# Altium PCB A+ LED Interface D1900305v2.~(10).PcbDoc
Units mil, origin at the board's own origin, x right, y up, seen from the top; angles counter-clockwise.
Board outline 2700 x 2000 mil, 4 copper layers (Top Layer, GND, GND (Plane2), Bottom Layer), stack 61.2 mil thick; 19 components, 34 nets, 90 pads, 1 vias.
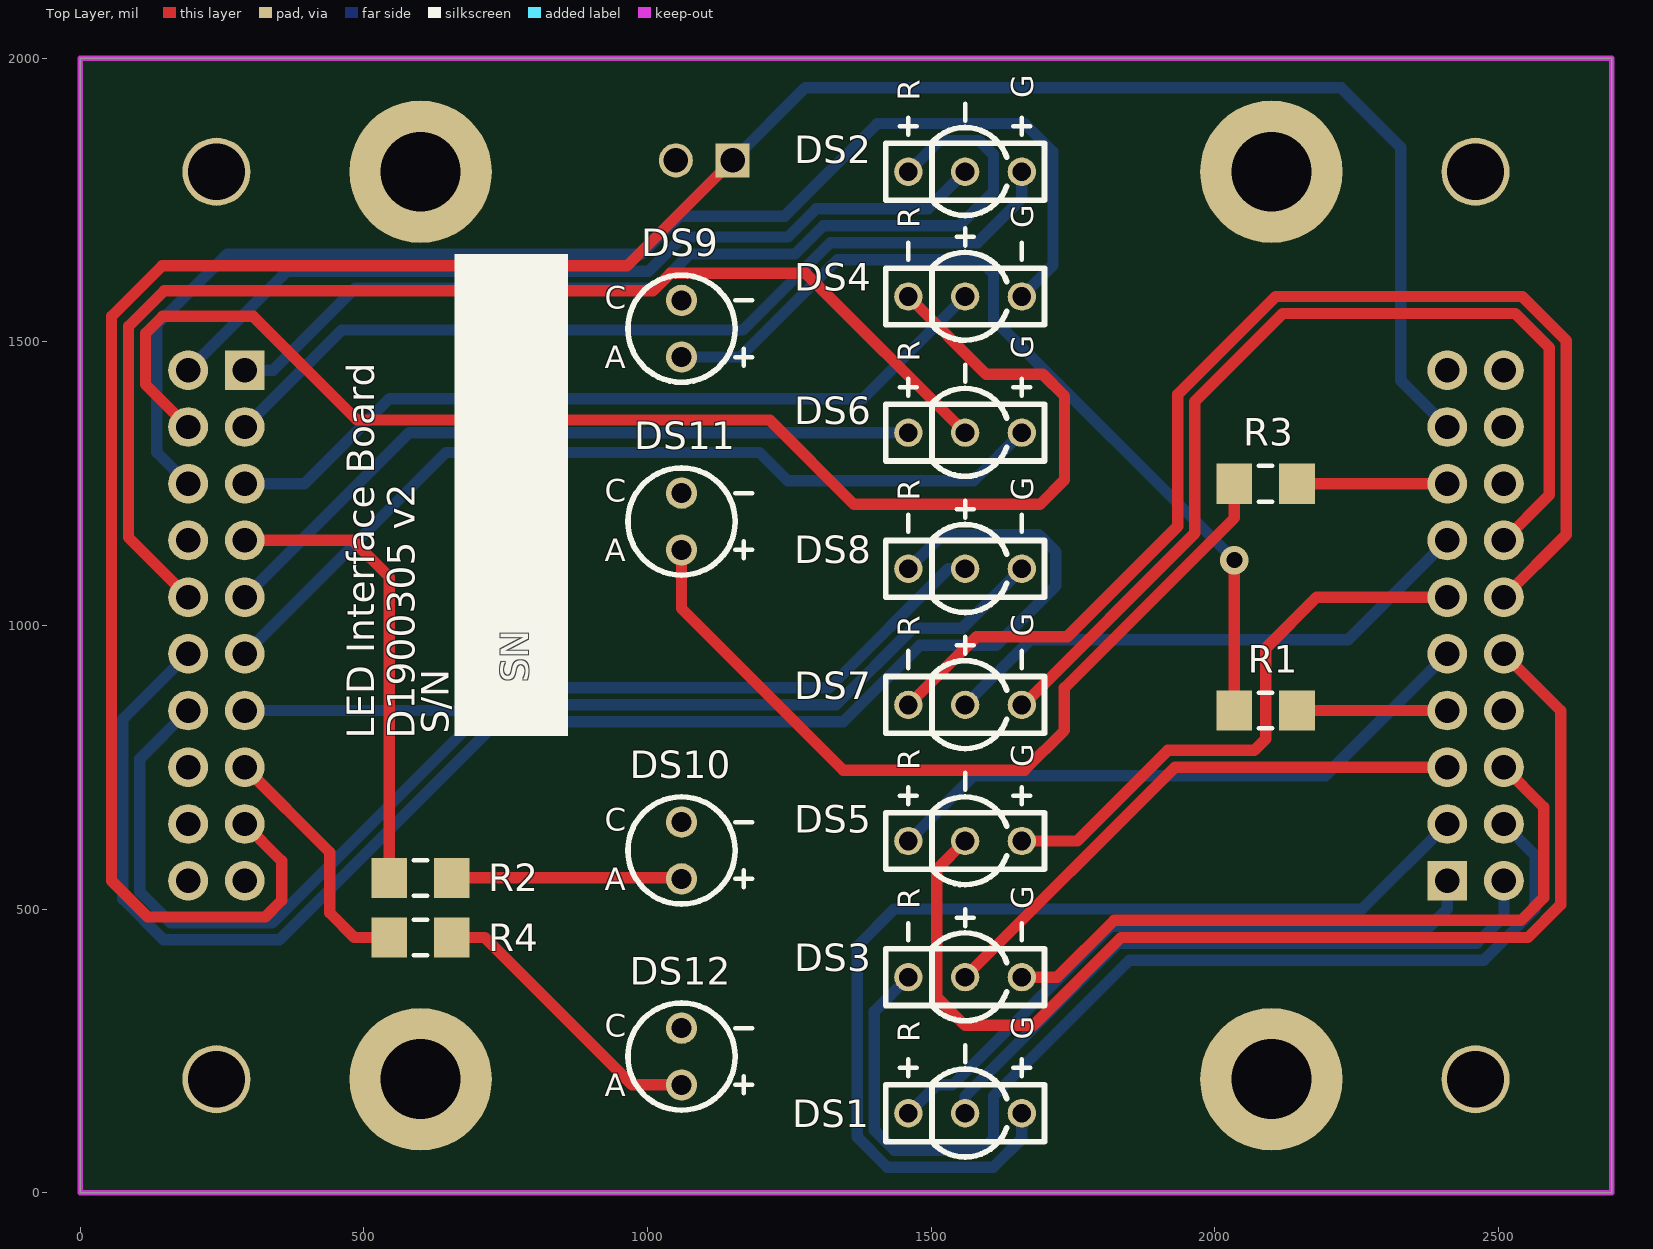
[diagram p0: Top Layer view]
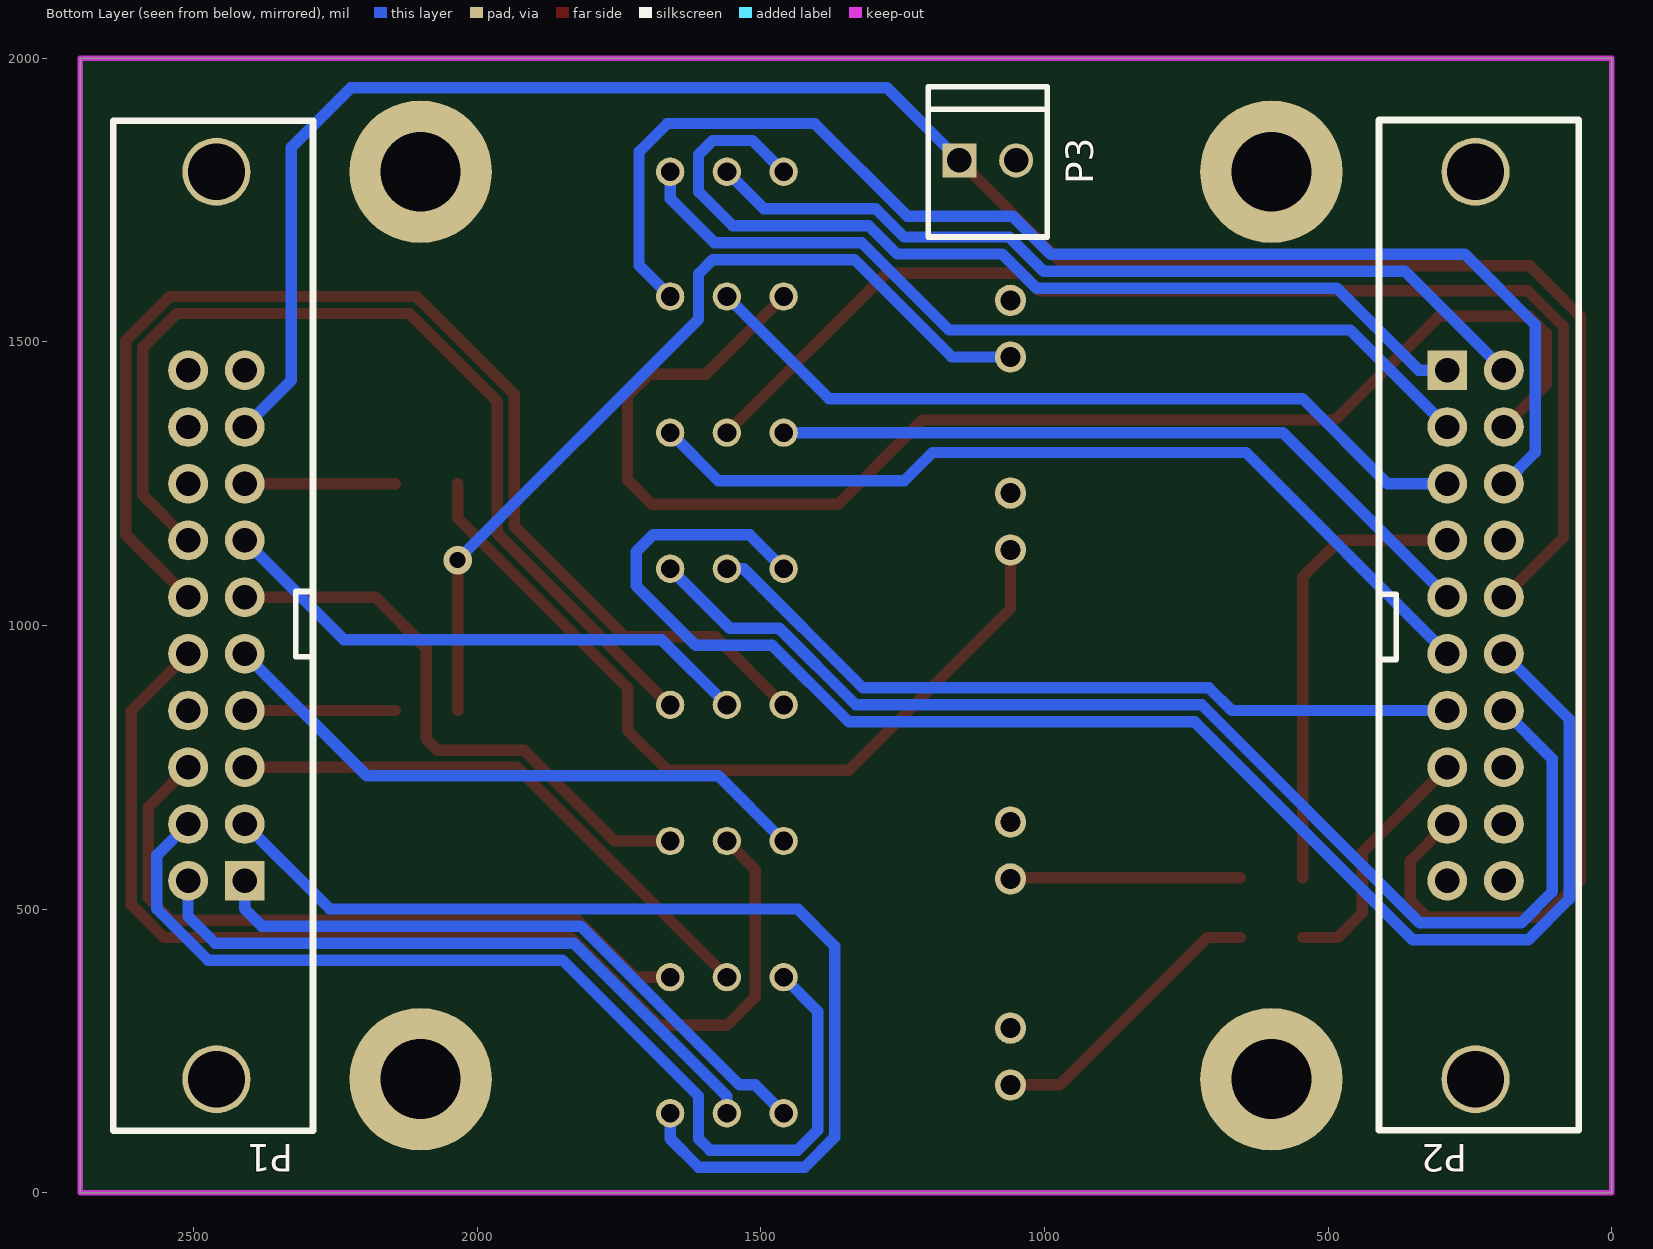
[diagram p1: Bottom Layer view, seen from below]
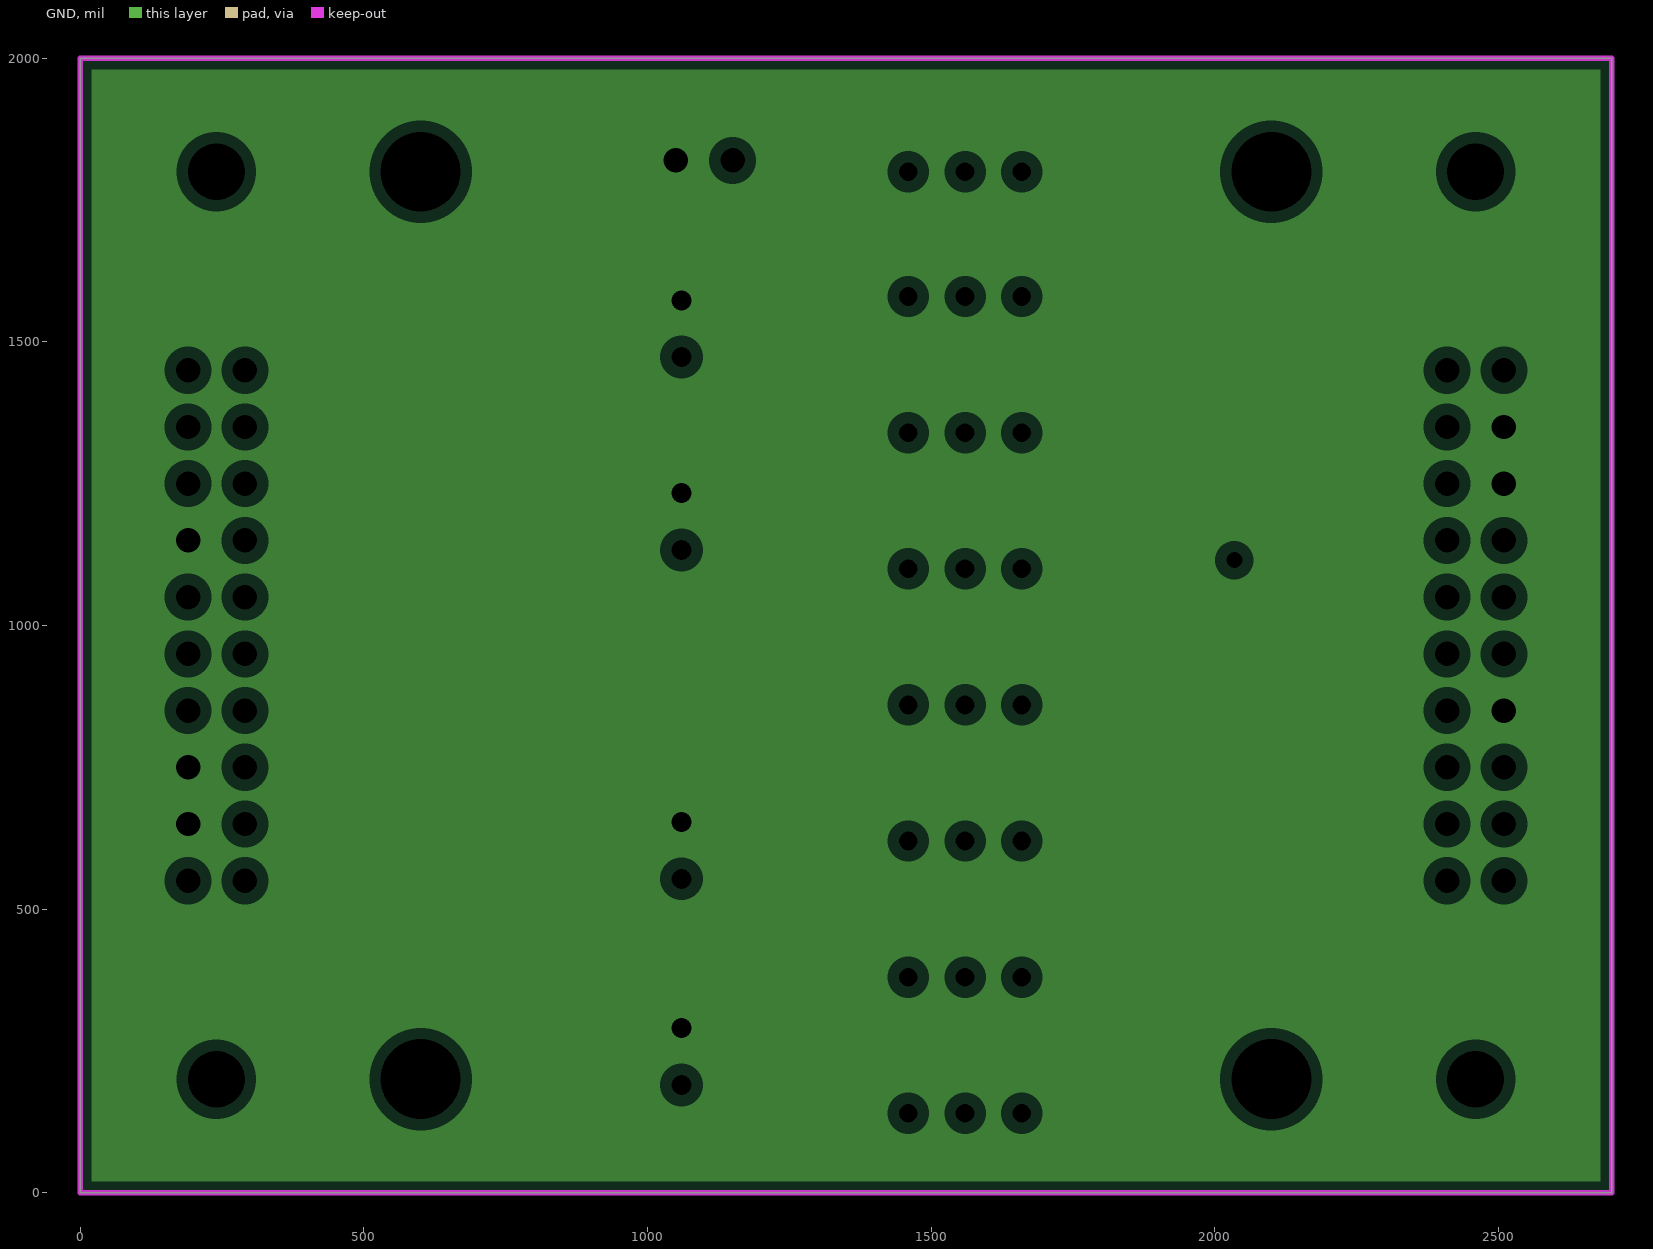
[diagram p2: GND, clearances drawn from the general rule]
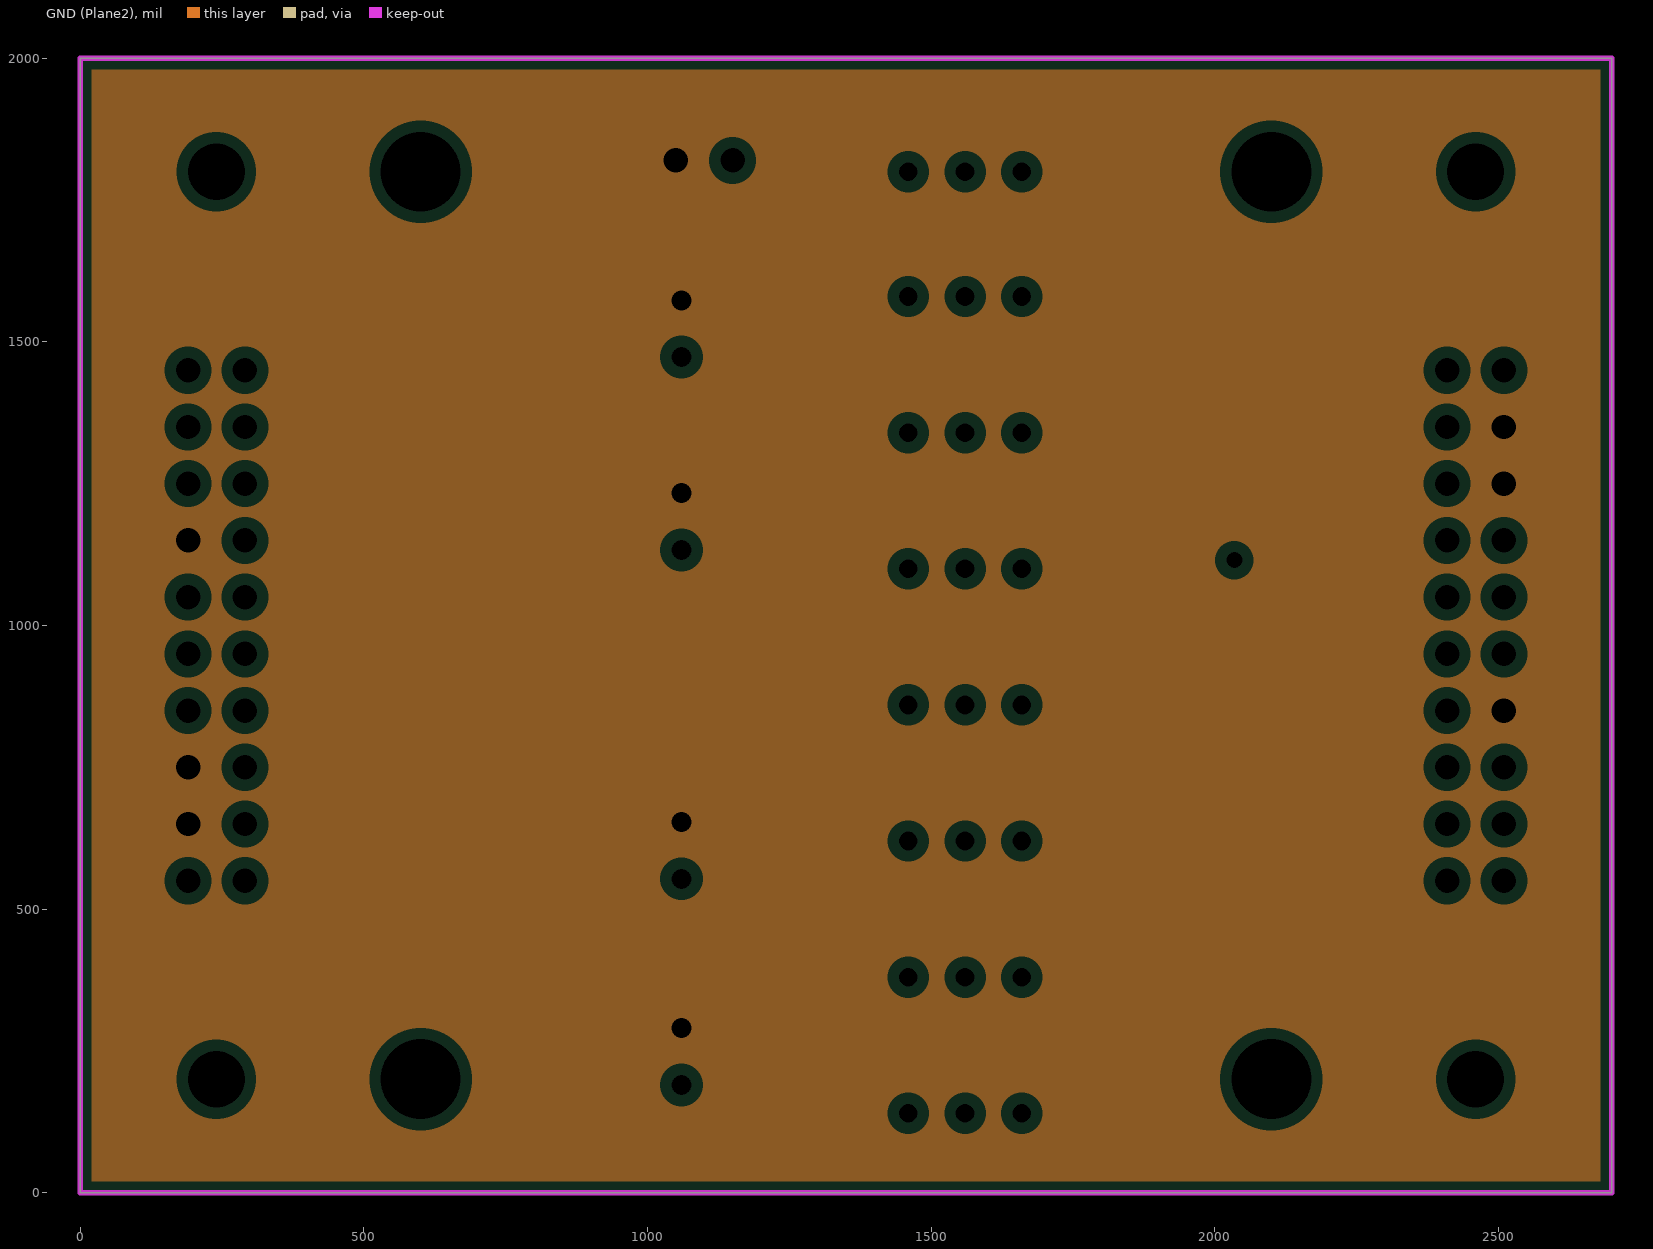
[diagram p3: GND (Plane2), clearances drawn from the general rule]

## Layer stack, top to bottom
Top Solder: solder mask 0.4, Solder Resist, Dk 3.5
Top Layer: signal copper 1.4
Dielectric 1: prepreg 7.5, FR-4, Dk 4.2
GND: plane copper 1.4, net GND
Dielectric 3: prepreg 40.6, Dk 4.2
GND (Plane2): plane copper 1.4, net GND
Dielectric 2: prepreg 7.5, FR-4, Dk 4.2
Bottom Layer: signal copper 1.4
Bottom Solder: solder mask 0.4, Solder Resist, Dk 3.5

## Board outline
0,0 2700,0 2700,2000 0,2000 0,0

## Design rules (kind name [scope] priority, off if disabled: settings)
Clearance [All] p1: gap=10 ignorepadtopadclearanceinfootprint=FALSE except(0: Arc-Hole Track-Hole SMDPad-Hole THPad-Hole Via-Hole Fill-Hole Poly-Hole Region-Hole Text-Hole)
FabricationTestPointUsage TestPointUsage [All] p1: valid=0 allowmultiple=FALSE
FabricationTestpoint Testpoint [All] p1: side=3 testpointundercomponent=TRUE minsize=40 maxsize=100 preferedsize=60 minholesize=0 maxholesize=40 preferedholesize=32 testpointgrid=1 allowsidetop=TRUE allowsidebottom=TRUE usegrid=TRUE gridtolerance=0.01
Height [All] p1: minheight=0 maxheight=2000 prefheight=2000
HoleSize [All] p1: absolutevalues=TRUE maxlimit=300 minlimit=1 maxpercent=80.000 minpercent=20.000
PlaneClearance [All] p1: clearance=20
PlaneConnect [All] p1: planeconnectstyle=Relief reliefexpansion=20 reliefentries=4 reliefconductorwidth=10 reliefairgap=10
PolygonConnect [All] p1: connectstyle=Relief reliefconductorwidth=10 reliefentries=4 polygonreliefangle="90 Angle" airgapwidth=10
RoutingVias [All] p1: holewidth=28 width=50 viastyle="Through Hole" minholewidth=28 minwidth=50 maxholewidth=28 maxwidth=50
SolderMaskExpansion [All] p1: expansion=4
Width [All] p1: maxlimit=50 minlimit=10 preferedwidth=20 minimp=50.000000 maximp=50.000000 favimp=50.000000
24 further rules are at their usual default settings.

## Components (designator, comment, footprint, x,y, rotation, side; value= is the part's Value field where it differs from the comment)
DS1 "DUAL_LED+" "COM_CATHODE LED" 1560,140 r90 top
DS2 "DUAL_LED+" "COM_CATHODE LED" 1560,1800 r90 top
DS3 "DUAL_LED-" "LED R/G Comm Anode (+)" 1560,380 r90 top
DS4 "DUAL_LED-" "LED R/G Comm Anode (+)" 1560,1580 r90 top
DS5 "DUAL_LED+" "COM_CATHODE LED" 1560,620 r90 top
DS6 "DUAL_LED+" "LED R/G COMM CATHODE (-)" 1560,1340 r90 top
DS7 "DUAL_LED-" "LED R/G Comm Anode (+)" 1560,860 r90 top
DS8 "DUAL_LED-" "LED R/G Comm Anode (+)" 1560,1100 r90 top
DS9 "LED0" RED_LED 1060,1523.3 r0 top
DS10 "LED0" RED_LED 1060,603.3 r0 top
DS11 "LED0" RED_LED 1060,1183.3 r0 top
DS12 "LED0" RED_LED 1060,240 r0 top
P1 "Header 20" "IDC 20 _VERTICAL" 2460,1000 r90 bottom
P2 "Header 20" "IDC 20 _VERTICAL" 240,1000 r270 bottom
P3 "Molex 2 PIN" "2PIN_MOLEX 100 MIL" 1100,1820 r180 bottom
R1 "1K" 3216[1206] 2089.88,850 r180 top
R2 "1K" 3216[1206] 600,555 r0 top
R3 "1K" 3216[1206] 2089.88,1250 r180 top
R4 "1K" 3216[1206] 600,450 r0 top

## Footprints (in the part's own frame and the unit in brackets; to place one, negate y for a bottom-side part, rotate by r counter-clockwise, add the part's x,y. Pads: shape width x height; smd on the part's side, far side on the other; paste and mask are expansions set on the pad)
"2PIN_MOLEX 100 MIL" [mil]
  rect 60x60 hole 43: 1(-50,0)
  round 60 hole 43: 2(50,0)
  silkscreen extent -105,-135 105,130, body extent -97,-128 97,122, height 421
3216[1206] [mm] "Chip Resistor; Body 3.2 x 1.6 mm (LxW typ)"
  rect 1.6x1.8 smd: 1(-1.4,0) 2(1.4,0)
  silkscreen extent -0.3,-0.8 0.3,0.8, body extent -1.6,-0.8 1.6,0.8, height 0.55
"COM_CATHODE LED" [mil]
  round 50 hole 33: 1(0,100) 2(0,0) 3(0,-100)
  silkscreen extent -77,-140 120,140, body extent -80,-110 80,110, height 305
"IDC 20 _VERTICAL" [mil]
  round 120 hole 100: 0(-800,0) 0(800,0)
  rect 70x70 hole 43: 1(-450,-50)
  round 70 hole 43: 2(-450,50) 3(-350,-50) 4(-350,50) 5(-250,-50) 6(-250,50) 7(-150,-50) 8(-150,50) 9(-50,-50) 10(-50,50) 11(50,-50) 12(50,50) 13(150,-50) 14(150,50) 15(250,-50) 16(250,50) 17(350,-50) 18(350,50) 19(450,-50) 20(450,50)
  silkscreen extent -891,-170 890,182, body extent -881,-159 879,172, height 1044
"LED R/G Comm Anode (+)" [mil]
  round 50 hole 33: 1(0,100) 2(0,0) 3(0,-100)
  silkscreen extent -77,-140 120,140, body extent -80,-110 80,110, height 305
"LED R/G COMM CATHODE (-)" [mil]
  round 50 hole 33: 1(0,100) 2(0,0) 3(0,-100)
  silkscreen extent -77,-140 120,140, body extent -80,-110 80,110, height 305
RED_LED [mm]
  round 1.4 hole 0.9: 1(0,-1.27) 2(0,1.27)
  silkscreen extent -2.4,-2.4 3.17,2.4, body extent -1.6,-1.62 1.6,1.62, height 7.14

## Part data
DS1 DS2 DS5: "Green, Red  LED Indication - Discrete 2.2V Green, 2V Red Radial - 3 Leads", Case/Package=Radial, Color=Green,Red, Forward Current=150mA, Forward Voltage=2V, Lens Color=White, Manufacturer=Lumex, Manufacturer Part Number=SSL-LX3059IGW, Max Operating Temperature=85°C, Min Operating Temperature=-40°C, Package Quantity=1000, Power Dissipation=105mW, Supplier Part Number 1=67-1327-ND, Test Current=20mA
DS3 DS4 DS7 DS8: library part "DUAL_LED Comm Anode", "Green, Red  LED Indication - Discrete 2.2V Green, 2V Red Radial - 3 Leads", Color=Green,Red, Forward Current=20mA, Forward Voltage=2.2V, Manufacturer=Lumex, Manufacturer Part Number=SSL-LX3059IGW-CA, Max Operating Temperature=85°C, Min Operating Temperature=-40°C, Package Quantity=1000, Supplier Part Number 1=67-2307-ND
DS6: library part "DUAL_LED Comm Cathode", "Green, Red  LED Indication - Discrete 2.2V Green, 2V Red Radial - 3 Leads", Case/Package=Radial, Color=Green,Red, Forward Current=150mA, Forward Voltage=2V, Lens Color=White, Manufacturer=Lumex, Manufacturer Part Number=SSL-LX3059IGW, Max Operating Temperature=85°C, Min Operating Temperature=-40°C, Package Quantity=1000, Power Dissipation=105mW, Supplier Part Number 1=67-1327-ND, Test Current=20mA
DS9 DS10 DS11 DS12: "Red 640nm LED Indication - Discrete 1.85V Radial", Case/Package=Radial, Color=Red, Forward Current=20mA, Forward Voltage=1.85V, Manufacturer=Kingbright, Manufacturer Part Number=WP710A10SRD/F, Max Operating Temperature=85°C, Min Operating Temperature=-40°C, Package Quantity=1000, Supplier Part Number 1=754-1725-ND
P1 P2: "Header, 20-Pin", Color=Grey, Current Rating=1A, Flammability Rating="UL94 V-0", Insulation Resistance=100GR, Manufacturer="Amphenol FCI", Manufacturer Part Number=71918-120LF, Max Operating Temperature=125°C, Max Voltage Rating (AC)=1.5kV, Min Operating Temperature=-65°C, Package Quantity=11, Supplier Part Number 1=609-1755-ND
P3: library part "Header 2H", "Header, 2-Pin, Right Angle", Color=White, Contact Resistance=10mR, Current Rating=4A, Flammability Rating="UL94 V-0", Housing Color=Black, Insulation Resistance=50GR, Manufacturer=Molex, Manufacturer Part Number=22-11-2022, Max Current Rating=7A, Max Operating Temperature=75°C, Max Voltage Rating (AC)=250V, Min Operating Temperature=0°C, Package Quantity=3000, Supplier Part Number 1=WM2700-ND
R1 R2 R3 R4: library part "Res Semi", "Semiconductor Resistor", Case/Package=1206, Case Code (Metric)=3216, Manufacturer=Panasonic, Manufacturer Part Number=ERJ-8ENF1001V, Max Operating Temperature=155°C, Max Power Dissipation=250mW, Min Operating Temperature=-55°C, Package Quantity=1, Resistance=1kR, Supplier Part Number 1=P1.00KFCT-ND, Temperature Coefficient=100ppm/°C, Tolerance=1%, Voltage Rating=200V

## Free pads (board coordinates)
  round 251 hole 141: 1(600,200) 2(2100,200) 3(2100,1800) 4(600,1800)

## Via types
v1: diameter 50, hole 28, Top Layer to Bottom Layer, 1 vias

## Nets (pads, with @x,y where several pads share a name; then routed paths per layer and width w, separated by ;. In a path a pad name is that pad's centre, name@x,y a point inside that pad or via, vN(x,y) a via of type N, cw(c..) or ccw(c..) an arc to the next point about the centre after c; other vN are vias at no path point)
GND: DS9.2 DS10.2 DS11.2 DS12.2 P1.8 P1.16 P1.18 P2.8 P2.16 P2.18 P3.2
NetDS1_1: DS1.1 P1.1 | length 1149.1
  Bottom Layer w20: DS1.1 1510,190 1537.57,190 1817.57,470 2380,470 2410,500 P1.1
NetDS1_2: DS1.2 P1.2 | length 1174.1
  Bottom Layer w20: DS1.2 1560,170 1830,440 2462.57,440 2510,487.43 P1.2
NetDS1_3: DS1.3 P1.3 | length 1844
  Bottom Layer w20: DS1.3 1660,95 1610,45 1422.57,45 1370,97.57 1370,435 1435,500 2260,500 P1.3
NetDS2_1: DS2.1 P2.1 | length 1698.6
  Bottom Layer w20: P2.1 340,1450 484.5,1594.5 1013.94,1594.5 1074.48,1655.04 1260.19,1655.04 1310.15,1705 1550,1705 1610,1765 1610,1830 1585,1855 1515,1855 DS2.1
NetDS2_2: DS2.2 P2.2 | length 1515
  Bottom Layer w20: P2.2 364.5,1624.5 1001.51,1624.5 1062.05,1685.04 1247.76,1685.04 1297.72,1735 1495,1735 DS2.2
NetDS2_3: DS2.3 P2.3 | length 1584.2
  Bottom Layer w20: P2.3 460.86,1520.86 1168.43,1520.86 1322.57,1675 1582.43,1675 1660,1752.57 DS2.3
NetDS3_1: DS3.1 P1.4 | length 1867.2
  Bottom Layer w20: DS3.1 1400,320 1400,110 1435,75 1590,75 1610,95 1610,170.15 1849.85,410 2475,410 2565,500 2565,595 P1.4
NetDS3_2: DS3.2 P1.5 | length 1003.3
  Top Layer w20: DS3.2 1930,750 P1.5
NetDS3_3: DS3.3 P1.6 | length 1237
  Top Layer w20: DS3.3 1722.57,380 1822.57,480 2540,480 2580,520 2580,680 P1.6
NetDS4_1: DS4.1 P2.4 | length 2479.5
  Top Layer w20: P2.4 115,1425 115,1515 145,1545 305,1545 487.8,1362.2 1215.55,1362.2 1364.17,1213.58 1691.93,1213.58 1735.24,1256.89 1735.24,1404.53 1696.85,1442.91 1597.09,1442.91 DS4.1
NetDS4_2: DS4.2 P2.5 | length 1406.7
  Bottom Layer w20: P2.5 395,1250 545,1400 1377.57,1400 1380,1400 DS4.2
NetDS4_3: DS4.3 P2.6 | length 2328.7
  Bottom Layer w20: P2.6 135,1305 135,1530.71 258.79,1654.5 989.09,1654.5 1056.05,1721.46 1241.75,1721.46 1405.29,1885 1665,1885 1715,1835 1715,1635 DS4.3
NetDS5_1: DS5.1 P1.9 | length 1086.7
  Bottom Layer w20: DS5.1 1575,735 2195,735 P1.9
NetDS5_2: DS5.2 P1.10 | length 1988.3
  Top Layer w20: DS5.2 1510,570 1510,345 1560,295 1680,295 1835,450 2552.43,450 2610,507.57 2610,850 P1.10
NetDS5_3: DS5.3 P1.11 | length 1021.8
  Top Layer w20: DS5.3 1757.58,620 1917.58,780 2070,780 2090,800 2090,960 2180,1050 P1.11
NetDS6_1: DS6.1 P2.9 | length 1290.1
  Bottom Layer w20: P2.9 580,1340 DS6.1
NetDS6_2: DS6.2 P2.10 | length 2151
  Top Layer w20: P2.10 85,1155 85,1527.43 147.57,1590 1009.44,1590 1040.3,1620.86 1279.14,1620.86 DS6.2
NetDS6_3: DS6.3 P2.11 | length 1573
  Bottom Layer w20: P2.11 645,1305 1197.57,1305 1247.57,1255 1575,1255 DS6.3
NetDS7_1: DS7.1 P1.12 | length 2124.5
  Top Layer w20: DS7.1 1580,980 1740,980 1935,1175 1935,1407.43 2107.57,1580 2542.43,1580 2620,1502.43 2620,1160 P1.12
NetDS7_2: DS7.2 P1.13 | length 970.1
  Bottom Layer w20: DS7.2 1675,975 2235,975 P1.13
NetDS7_3: DS7.3 P1.14 | length 1749.9
  Top Layer w20: DS7.3 1662.43,860 1965,1162.57 1965,1395 2120,1550 2530,1550 2590,1490 2590,1230 P1.14
NetDS8_1: DS8.1 P2.12 | length 2770.5
  Bottom Layer w20: P2.12 75,835 75,517.57 146.57,446 351,446 735,830 1345,830 1480,965 1615,965 1720,1070 1720,1130 1690,1160 1520,1160 DS8.1
NetDS8_2: DS8.2 P2.13 | length 1373.6
  Bottom Layer w20: P2.13 670,850 710,890 1320.15,890 1530.14,1100 DS8.2
NetDS8_3: DS8.3 P2.14 | length 2191
  Bottom Layer w20: P2.14 105,765 105,530 159,476 338.57,476 722.57,860 1332.57,860 1467.57,995 1555,995 DS8.3
NetDS9_1: DS9.1 R1.2 | length 1577.4
  Top Layer w20: R1.2 v1(2034.76,1115.24)
  Bottom Layer w20: DS9.1 1163.3,1473.3 1335,1645 1585,1645 1610,1620 1610,1540 v1(2034.76,1115.24)
NetDS10_1: DS10.1 R2.2 | length 405.9
  Top Layer w20: R2.2 1058.3,555 cw(c1058.3,553.3) DS10.1
NetDS11_1: DS11.1 R3.2 | length 1484.5
  Top Layer w20: DS11.1 1060,1030 1345,745 1665,745 1735,815 1735,890 2034.76,1189.76 R3.2
NetDS12_1: DS12.1 R4.2 | length 512.6
  Top Layer w20: R4.2 713,450 973,190 DS12.1
NetP1_7: P1.7 R1.1 | length 265
  Top Layer w20: R1.1 P1.7
NetP1_15: P1.15 R3.1 | length 265
  Top Layer w20: R3.1 P1.15
NetP1_17: P1.17 P2.17 P3.1 | length 4505.8
  Top Layer w20: P2.17 355,585 355,515 326,486 119,486 55,550 55,1545 144,1634 964,1634 P3.1
  Bottom Layer w20: P3.1 1278,1948 2223,1948 2328,1843 2328,1432 P1.17
NetP2_7: P2.7 R2.1 | length 812
  Top Layer w20: P2.7 480.24,1150 544.88,1085.36 R2.1
NetP2_15: P2.15 R4.1 | length 441.8
  Top Layer w20: P2.15 440,600 440,493 483,450 R4.1
pads on no net: P1.0 P1.19 P1.20 P2.0 P2.19 P2.20

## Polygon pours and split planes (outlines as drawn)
GND on GND (split plane): 2679.9,20.1 20.1,20.1 20.1,1979.9 2679.9,1979.9
GND on GND (Plane2) (split plane): 2679.9,20.1 20.1,20.1 20.1,1979.9 2679.9,1979.9

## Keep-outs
Keep-Out Layer:
  the board outline again, w10

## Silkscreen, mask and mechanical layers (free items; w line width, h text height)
Top Overlay:
  region: 860,805 860,1655 660,1655 660,805
  text "SN" at 790,900 h48 r90
  text "S/N" at 650,809.5 h48 r90
  text "LED Interface Board / D1900305 v2" at 590,800 h48 r90
Mechanical 1:
  the board outline again, w8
